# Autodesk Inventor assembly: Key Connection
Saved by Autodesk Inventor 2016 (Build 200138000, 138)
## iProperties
Created: 2015-08
Part Number: Key Connection
Document SubType Name: Assembly
Designer: stank
Mass: 5.68026 g
Surface Area: 5.14753 cm^2
Volume: 0.7236 cm^3
Density: 7.85 g/cm^3
ClientObjectVersion: 1
Author: stank
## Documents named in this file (2)
- E:\Turbokompr\Sklop turbokompresora\Design Accelerator\Key Connection5.iam
- C:\Users\stank\Documents\Inventor\Content Center Files\R2016\en-US\ISO 2491 - A\ISO 2491 - A  8 x 5 x 20.ipt
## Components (1 placed, 1 different names)
1. ISO 2491 A A  8 x 5 x 20:1
